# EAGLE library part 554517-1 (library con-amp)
AMP connector
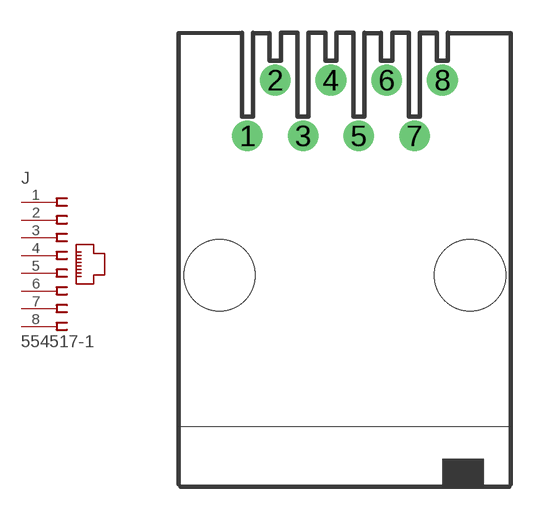
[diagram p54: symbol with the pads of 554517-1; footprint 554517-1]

Designator prefix J

## 554517-1 (MF: TYCO ELECTRONICS; MPN: 5554517-1; OC_FARNELL: 1764702; OC_NEWARK: 42K7297)  [554517-1]
1  1  pas
2  2  pas
3  3  pas
4  4  pas
5  5  pas
6  6  pas
7  7  pas
8  8  pas

## Footprint 554517-1 (pad centres in mm)
Modular Jack Keyed without Panel Stops
drill 0.889 round: 1 -4.445,6.35; 2 -3.175,8.89; 3 -1.905,6.35; 4 -0.635,8.89; 5 0.635,6.35; 6 1.905,8.89; 7 3.175,6.35; 8 4.445,8.89
hole 3.251 at -5.715,0
hole 3.251 at 5.715,0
